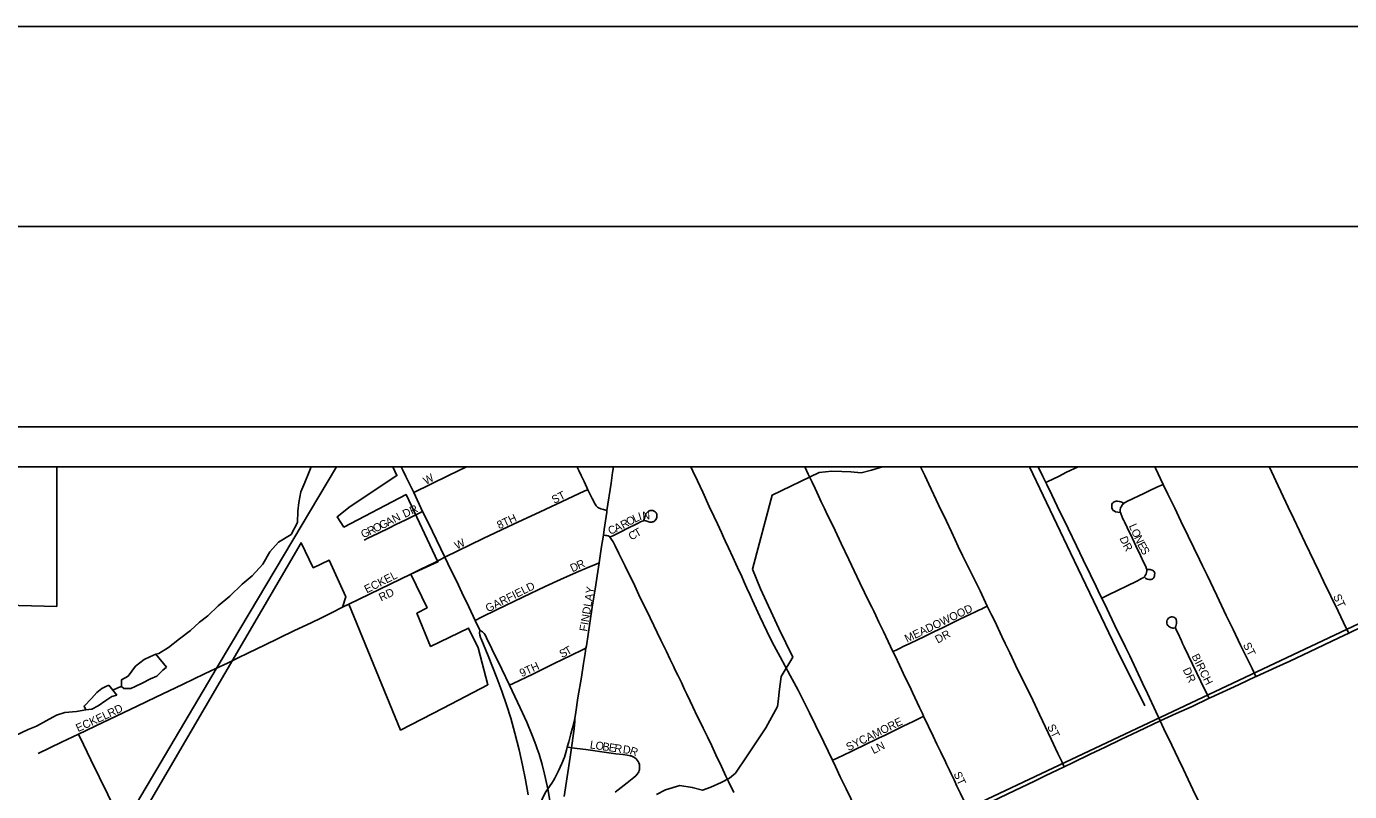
# Model space of a CAD drawing. Extents: x -5.6 to 34, y 0 to 22.
# Drawn here: x 3.152 to 6.458, y 20.089 to 22 of the extents above; entities that cross this region are included whole.
import ezdxf

# ---------------------------------------------------------------- set-up
doc = ezdxf.new("R2010")
doc.units = 0
for name, color, linetype in [('GM_X_City_Street', 7, 'Continuous'), ('GM_X_City_Street_Text', 7, 'Continuous'), ('GM_X_Corporation', 7, 'Continuous'), ('GM_X_Minor_Lake', 7, 'Continuous'), ('GM_X_Minor_River', 7, 'Continuous'), ('GM_X_Rail_Line', 7, 'Continuous'), ('GM_X_Section', 7, 'Continuous'), ('GM_X_State_Route', 7, 'Continuous'), ('GM_X_Township', 7, 'Continuous'), ('GM_X_Township_Road', 7, 'Continuous'), ('GM_X_Township_Subdivision', 7, 'Continuous'), ('GM_X_Township_Subdivision_Text', 7, 'Continuous'), ('SH_Border', 7, 'Continuous'), ('SH_Cut_Line', 7, 'Continuous'), ('SH_Data', 7, 'Continuous')]:
    doc.layers.add(name, color=color, linetype=linetype)

msp = doc.modelspace()

# ---------------------------------------------------------------- linework, layer by layer
at = {"layer": 'GM_X_City_Street'}
for points in [[(4.1194, 20.8356), (4.2063, 20.8782), (4.2512, 20.9)], [(4.5545, 20.8429), (4.5518, 20.8487), (4.5452, 20.8629), (4.5378, 20.8783), (4.5317, 20.8911), (4.5278, 20.8991), (4.5274, 20.9)], [(4.6024, 20.7906), (4.6129, 20.8588), (4.6166, 20.886), (4.6188, 20.9)], [(5.1659, 20.1669), (5.1441, 20.2122), (5.1236, 20.255), (5.1089, 20.2857), (5.0887, 20.3252), (5.0799, 20.3422), (5.0607, 20.379), (5.0351, 20.4251), (5.0153, 20.4621), (5.0021, 20.4891), (4.9845, 20.526), (4.9702, 20.557), (4.9658, 20.5664), (4.9599, 20.5793), (4.952, 20.5972), (4.9455, 20.6121), (4.9391, 20.6259), (4.9284, 20.6485), (4.9242, 20.6579), (4.9167, 20.6746), (4.9064, 20.6975), (4.8982, 20.7148), (4.8938, 20.7239), (4.8885, 20.7355), (4.8784, 20.7572), (4.8693, 20.7764), (4.8581, 20.8008), (4.8417, 20.8365), (4.8285, 20.865), (4.8168, 20.8893), (4.8118, 20.9)], [(5.3166, 20.4385), (5.2933, 20.4885), (5.2821, 20.5119), (5.2742, 20.5289), (5.2692, 20.5397), (5.2645, 20.5494), (5.2587, 20.5605), (5.2463, 20.5863), (5.2346, 20.6098), (5.2205, 20.6402), (5.2073, 20.6684), (5.188, 20.7085), (5.1726, 20.7406), (5.16, 20.7666), (5.1538, 20.7795), (5.1459, 20.7957), (5.1374, 20.8129), (5.131, 20.8276), (5.1227, 20.8455), (5.1151, 20.8613), (5.1052, 20.8815), (5.0966, 20.9)], [(5.553, 20.552), (5.535, 20.5898), (5.5237, 20.6135), (5.511, 20.6388), (5.4996, 20.6619), (5.4914, 20.6783), (5.4805, 20.701), (5.4723, 20.7178), (5.4637, 20.7377), (5.4508, 20.7638), (5.431, 20.8054), (5.4066, 20.8564), (5.3965, 20.8781), (5.386, 20.9)], [(5.6989, 20.8611), (5.7043, 20.8637), (5.7306, 20.8761), (5.7512, 20.8863), (5.7799, 20.9)], [(5.9923, 20.8561), (5.973, 20.8965), (5.9713, 20.9)], [(6.4565, 20.4841), (6.4502, 20.4971), (6.4295, 20.5397), (6.4113, 20.5772), (6.3931, 20.6147), (6.3806, 20.6406), (6.3697, 20.6631), (6.3473, 20.7097), (6.3187, 20.7701), (6.3047, 20.7996), (6.2739, 20.8646), (6.258, 20.8994), (6.2578, 20.9)], [(4.1976, 20.674), (4.2932, 20.7208), (4.3687, 20.7564), (4.4358, 20.7877), (4.5026, 20.8188), (4.5474, 20.8396), (4.5545, 20.8429)], [(4.6024, 20.7906), (4.5938, 20.7931), (4.5868, 20.7951), (4.5815, 20.7972), (4.5786, 20.7992), (4.5753, 20.8027), (4.5728, 20.8067), (4.5655, 20.8207), (4.5614, 20.8289), (4.5596, 20.8323), (4.5562, 20.8393), (4.5545, 20.8429)], [(5.894, 20.8086), (5.8959, 20.8099), (5.9038, 20.8144), (5.9155, 20.8198), (5.9332, 20.8282), (5.9429, 20.8327), (5.9578, 20.8398), (5.9771, 20.8489), (5.9923, 20.8561)], [(6.2245, 20.3762), (6.2148, 20.3959), (6.1859, 20.4547), (6.1676, 20.4932), (6.1504, 20.5287), (6.1263, 20.5789), (6.1022, 20.6292), (6.0905, 20.6527), (6.0831, 20.6682), (6.0547, 20.7271), (6.0367, 20.7645), (6.0213, 20.7964), (6.0041, 20.8314), (5.9923, 20.8561)], [(5.8855, 20.7861), (5.8789, 20.7867), (5.8737, 20.7879), (5.8699, 20.7897), (5.8676, 20.7912), (5.8657, 20.7936), (5.8645, 20.7975), (5.864, 20.8011), (5.8641, 20.8039), (5.8646, 20.8067), (5.8659, 20.8092), (5.8672, 20.8106), (5.8697, 20.8125), (5.8726, 20.8137), (5.8752, 20.814), (5.878, 20.8141), (5.8829, 20.8134), (5.8867, 20.8124), (5.8905, 20.8108), (5.894, 20.8086)], [(5.8855, 20.7861), (5.8852, 20.7893), (5.8852, 20.7911), (5.8854, 20.7929), (5.8863, 20.7973), (5.8881, 20.801), (5.8902, 20.8048), (5.894, 20.8086)], [(4.5934, 20.7292), (4.5956, 20.7437), (4.6018, 20.7866), (4.6024, 20.7906)], [(4.6099, 20.724), (4.6205, 20.7294), (4.6334, 20.736), (4.6578, 20.7482), (4.6721, 20.7554), (4.68, 20.7596), (4.686, 20.7627), (4.6902, 20.7643), (4.6937, 20.7654), (4.6966, 20.7656), (4.6995, 20.7653), (4.7048, 20.7635), (4.7095, 20.762), (4.7111, 20.7618), (4.7129, 20.7617), (4.7147, 20.7619), (4.7163, 20.7623), (4.7178, 20.7628), (4.7195, 20.7636), (4.721, 20.7645), (4.7224, 20.7656), (4.7237, 20.7669), (4.7247, 20.7682), (4.7256, 20.7696), (4.7264, 20.7713), (4.727, 20.7731), (4.7272, 20.7746), (4.7274, 20.7764), (4.7274, 20.7781), (4.7271, 20.7799), (4.7267, 20.7815), (4.7261, 20.7831), (4.7253, 20.7847), (4.7244, 20.7861), (4.7232, 20.7874), (4.7205, 20.7893), (4.7191, 20.7899), (4.7172, 20.7905), (4.7137, 20.7911), (4.7103, 20.7908), (4.7087, 20.7904), (4.7071, 20.7897), (4.7055, 20.7887), (4.7043, 20.7878), (4.7018, 20.7852), (4.6999, 20.7827), (4.6987, 20.7803), (4.6981, 20.7787), (4.6975, 20.7772), (4.6948, 20.7663)], [(5.9513, 20.6438), (5.951, 20.6454), (5.9489, 20.651), (5.9437, 20.6619), (5.9356, 20.6788), (5.924, 20.703), (5.9155, 20.721), (5.9025, 20.7482), (5.8955, 20.7627), (5.8941, 20.7656), (5.8921, 20.7698), (5.8864, 20.7831), (5.8855, 20.7861)], [(4.583, 20.6603), (4.5891, 20.7009), (4.5934, 20.7292)], [(4.6099, 20.724), (4.6093, 20.7247), (4.6074, 20.7264), (4.6051, 20.7277), (4.6022, 20.7283), (4.5985, 20.7287), (4.5934, 20.7292)], [(4.9193, 20.0864), (4.9062, 20.1142), (4.8997, 20.1274), (4.8886, 20.1512), (4.8749, 20.1806), (4.8645, 20.2028), (4.8536, 20.2251), (4.8428, 20.247), (4.837, 20.2593), (4.8282, 20.2774), (4.8173, 20.3), (4.81, 20.3146), (4.8018, 20.3319), (4.7965, 20.3436), (4.7883, 20.3609), (4.7793, 20.3798), (4.7724, 20.3939), (4.7685, 20.4022), (4.7607, 20.4188), (4.7512, 20.4389), (4.7374, 20.467), (4.7105, 20.5225), (4.6824, 20.5804), (4.6684, 20.61), (4.6578, 20.6312), (4.6478, 20.6517), (4.6322, 20.6837), (4.623, 20.7022), (4.6176, 20.7122), (4.6152, 20.7162), (4.6123, 20.7209), (4.6099, 20.724)], [(4.1119, 20.6319), (4.1355, 20.6433), (4.1719, 20.661), (4.1976, 20.674)], [(4.273, 20.516), (4.289, 20.524), (4.3261, 20.5426), (4.3919, 20.5743), (4.4478, 20.6007), (4.4861, 20.6183), (4.5252, 20.636), (4.5532, 20.648), (4.5751, 20.6571), (4.583, 20.6603)], [(4.55, 20.4468), (4.5509, 20.4531), (4.5552, 20.4809), (4.5656, 20.5496), (4.5731, 20.594), (4.5796, 20.6382), (4.583, 20.6603)], [(5.9451, 20.6251), (5.9467, 20.6269), (5.9479, 20.6286), (5.949, 20.6307), (5.95, 20.6328), (5.9509, 20.6356), (5.9515, 20.6398), (5.9515, 20.6426), (5.9513, 20.6438)], [(5.9451, 20.6251), (5.9494, 20.6209), (5.951, 20.6199), (5.953, 20.619), (5.9568, 20.6182), (5.9598, 20.6182), (5.9625, 20.6187), (5.9647, 20.6195), (5.9662, 20.6203), (5.9664, 20.6204), (5.9682, 20.6222), (5.9693, 20.6236), (5.9706, 20.6268), (5.9712, 20.6302), (5.9713, 20.6339), (5.9708, 20.6362), (5.9697, 20.6383), (5.9682, 20.64), (5.9667, 20.6411), (5.965, 20.6421), (5.9629, 20.643), (5.9597, 20.6436), (5.9551, 20.6437), (5.9513, 20.6438)], [(3.9572, 20.5568), (4.0086, 20.5819), (4.0863, 20.619), (4.1119, 20.6319)], [(5.839, 20.5716), (5.8527, 20.5783), (5.8819, 20.5926), (5.8995, 20.601), (5.9283, 20.6155), (5.9342, 20.6183), (5.9387, 20.6208), (5.9422, 20.6228), (5.9451, 20.6251)], [(3.6544, 20.4098), (3.679, 20.4217), (3.7069, 20.4354), (3.7462, 20.4547), (3.8196, 20.49), (3.8648, 20.5113), (3.887, 20.5219), (3.9138, 20.535), (3.9415, 20.549)], [(5.3166, 20.4385), (5.3248, 20.4423), (5.3336, 20.4464), (5.3427, 20.4509), (5.3592, 20.4589), (5.396, 20.476), (5.4195, 20.4874), (5.443, 20.499), (5.4842, 20.519), (5.5113, 20.532), (5.522, 20.537), (5.5338, 20.5424), (5.5385, 20.5446), (5.543, 20.5469), (5.553, 20.552)], [(5.7452, 20.1506), (5.7398, 20.1623), (5.7296, 20.1841), (5.7127, 20.22), (5.6838, 20.281), (5.6619, 20.3275), (5.6393, 20.3724), (5.6237, 20.4044), (5.609, 20.4351), (5.5979, 20.4589), (5.5894, 20.4765), (5.5715, 20.5144), (5.5634, 20.5303), (5.553, 20.552)], [(6.1071, 20.3217), (6.0979, 20.3409), (6.0452, 20.45), (6.0412, 20.4589), (6.0387, 20.4649), (6.0289, 20.4855), (6.0245, 20.4944), (6.0239, 20.4963), (6.0234, 20.4992), (6.0235, 20.5006), (6.0238, 20.502), (6.0247, 20.505), (6.0258, 20.5085), (6.0262, 20.511), (6.0262, 20.5144), (6.0254, 20.5187), (6.0238, 20.5212), (6.0215, 20.523), (6.0189, 20.5245), (6.0159, 20.525), (6.0137, 20.525), (6.011, 20.5246), (6.0084, 20.5236), (6.0061, 20.5219), (6.0042, 20.5198), (6.0028, 20.5174), (6.002, 20.5147), (6.0021, 20.509), (6.0028, 20.5064), (6.0042, 20.5039), (6.0061, 20.5018), (6.0084, 20.5001), (6.0112, 20.4987), (6.014, 20.4978), (6.0168, 20.4973), (6.019, 20.4972), (6.0226, 20.4974)], [(6.2245, 20.3762), (6.2247, 20.3763), (6.2755, 20.3995), (6.3087, 20.4147), (6.3582, 20.4374), (6.4318, 20.4724), (6.4565, 20.4841)], [(6.4565, 20.4841), (6.4603, 20.4858), (6.4871, 20.4992)], [(4.3589, 20.3542), (4.3677, 20.3585), (4.4168, 20.3824), (4.4707, 20.4085), (4.512, 20.4284), (4.543, 20.4434), (4.55, 20.4468)], [(4.5218, 20.2715), (4.5242, 20.287), (4.5299, 20.3233), (4.5386, 20.3744), (4.5441, 20.4084), (4.548, 20.4339), (4.55, 20.4468)], [(5.3938, 20.2769), (5.3907, 20.2836), (5.3833, 20.2989), (5.3663, 20.3358), (5.359, 20.3511), (5.3481, 20.3736), (5.3335, 20.4041), (5.3223, 20.4275), (5.3166, 20.4385)], [(3.2812, 20.2325), (3.3422, 20.2613), (3.4284, 20.3019), (3.475, 20.3242), (3.5416, 20.3562), (3.5964, 20.383), (3.6247, 20.3962), (3.6544, 20.4098)], [(6.1071, 20.3217), (6.1114, 20.3238), (6.1806, 20.3557), (6.2245, 20.3762)], [(5.9848, 20.2651), (6.0253, 20.2835), (6.0652, 20.3016), (6.1071, 20.3217)], [(4.5033, 20.1995), (4.5072, 20.2127), (4.5124, 20.2331), (4.516, 20.2477), (4.5218, 20.2715)], [(4.5139, 20.1982), (4.5188, 20.2342), (4.5202, 20.2453), (4.5213, 20.2557), (4.5217, 20.2633), (4.5218, 20.2715)], [(5.1659, 20.1669), (5.1779, 20.1725), (5.2131, 20.1892), (5.2549, 20.2094), (5.2691, 20.2163), (5.2828, 20.2227), (5.2959, 20.2289), (5.3214, 20.2413), (5.3428, 20.2517), (5.3676, 20.2637), (5.3873, 20.2736), (5.3938, 20.2769)], [(5.5095, 20.0372), (5.5046, 20.0469), (5.4971, 20.0616), (5.486, 20.0842), (5.4772, 20.1026), (5.4698, 20.1182), (5.4634, 20.1313), (5.4585, 20.1426), (5.4546, 20.1507), (5.4514, 20.1574), (5.4467, 20.1668), (5.4405, 20.1797), (5.4368, 20.1873), (5.427, 20.2075), (5.4179, 20.2268), (5.3946, 20.2753), (5.3938, 20.2769)], [(5.8869, 20.2187), (5.9291, 20.2387), (5.9848, 20.2651)], [(3.2812, 20.2325), (3.2388, 20.212), (3.1809, 20.184)], [(3.4074, 19.9733), (3.3902, 20.0079), (3.3759, 20.0378), (3.3552, 20.0811), (3.3122, 20.168), (3.2939, 20.2059), (3.2812, 20.2325)], [(5.8103, 20.1819), (5.8473, 20.1998), (5.8869, 20.2187)], [(4.4544, 20.0959), (4.4645, 20.1101), (4.4686, 20.1164), (4.4719, 20.1219), (4.4813, 20.1402), (4.4897, 20.1588), (4.4959, 20.175), (4.5012, 20.192), (4.5033, 20.1995)], [(4.4957, 20.0768), (4.5106, 20.1745), (4.5139, 20.1982)], [(4.5139, 20.1982), (4.5092, 20.1988), (4.5033, 20.1995)], [(4.623, 20.087), (4.6533, 20.1103), (4.6696, 20.1236), (4.6745, 20.1281), (4.6781, 20.1323), (4.6803, 20.1358), (4.6818, 20.1382), (4.6828, 20.1411), (4.6834, 20.1437), (4.6838, 20.1466), (4.6839, 20.1514), (4.6838, 20.1541), (4.6834, 20.1567), (4.6822, 20.1603), (4.6804, 20.1637), (4.6782, 20.1669), (4.6753, 20.1703), (4.6718, 20.1731), (4.6694, 20.1747), (4.6663, 20.1762), (4.6627, 20.1776), (4.66, 20.1782), (4.6531, 20.1794), (4.6418, 20.181), (4.6249, 20.1833), (4.6067, 20.1859), (4.5496, 20.1935), (4.5139, 20.1982)], [(5.7452, 20.1506), (5.7657, 20.1604), (5.8103, 20.1819)], [(5.2807, 19.9276), (5.2755, 19.9386), (5.2656, 19.9593), (5.2256, 20.042), (5.2118, 20.071), (5.2001, 20.0953), (5.1855, 20.1258), (5.1734, 20.1513), (5.1659, 20.1669)], [(5.6976, 20.1278), (5.7452, 20.1506)], [(5.5095, 20.0372), (5.5196, 20.042), (5.6047, 20.0832), (5.671, 20.1151), (5.6976, 20.1278)], [(4.4187, 19.9793), (4.4216, 19.9958), (4.4283, 20.0312), (4.4317, 20.045), (4.4361, 20.0589), (4.4405, 20.0696), (4.4447, 20.0787), (4.4499, 20.0884), (4.4544, 20.0959)]]:
    msp.add_lwpolyline(points, dxfattribs=at)
at = {"layer": 'GM_X_Corporation'}
for points in [[(2.8151, 20.562), (3.2274, 20.5511), (3.2277, 20.9), (2.1, 20.9)], [(8.2067, 20.9), (4.0671, 20.9), (4.0774, 20.8782), (3.9603, 20.8011), (3.9283, 20.7752), (3.945, 20.7493), (4.1004, 20.8306), (4.1798, 20.6626), (4.1119, 20.6319), (4.1528, 20.5478), (4.1273, 20.534), (4.1616, 20.4512), (4.2565, 20.497), (4.2803, 20.4477), (4.3047, 20.3554), (4.1931, 20.2971), (4.0865, 20.2422), (3.9572, 20.5568), (3.9415, 20.549), (3.9497, 20.5751), (3.9081, 20.6665), (3.8684, 20.6477), (3.8378, 20.7105), (3.4074, 19.9733)]]:
    msp.add_lwpolyline(points, dxfattribs=at)
at = {"layer": 'GM_X_Minor_Lake'}
for p, q in [((3.5016, 20.3991), (3.4752, 20.4318)), ((3.3778, 20.3299), (3.3576, 20.3544))]:
    msp.add_line(p, q, dxfattribs=at)
for points in [[(3.4752, 20.4318), (3.4599, 20.4257), (3.4454, 20.4189), (3.4242, 20.4017), (3.4061, 20.3773), (3.3891, 20.3681), (3.3887, 20.3513), (3.3949, 20.3463), (3.4125, 20.3459), (3.423, 20.3512), (3.4408, 20.3596), (3.4618, 20.3703), (3.4771, 20.3772), (3.4926, 20.392), (3.5016, 20.3991)], [(3.3576, 20.3544), (3.3503, 20.3514), (3.3398, 20.346), (3.3276, 20.3359), (3.3137, 20.321), (3.2956, 20.3022), (3.3002, 20.2933), (3.3146, 20.2945), (3.3308, 20.3029), (3.3503, 20.3161), (3.3649, 20.3262), (3.3778, 20.3299)]]:
    msp.add_lwpolyline(points, dxfattribs=at)
at = {"layer": 'GM_X_Minor_River'}
for points in [[(3.8635, 20.9), (3.8581, 20.8878), (3.8472, 20.8607), (3.8372, 20.8376), (3.8319, 20.8105), (3.8299, 20.7889), (3.8286, 20.7608), (3.8129, 20.7306), (3.7814, 20.712), (3.7602, 20.6875), (3.7421, 20.6566), (3.716, 20.6274), (3.6908, 20.607), (3.6599, 20.5771), (3.6308, 20.5528), (3.6047, 20.5276), (3.5837, 20.512), (3.5618, 20.4915), (3.5342, 20.4704), (3.5067, 20.4484), (3.4825, 20.4336)], [(5.2909, 20.9), (5.2638, 20.8913), (5.2374, 20.8853), (5.2119, 20.8874), (5.1896, 20.8886), (5.1648, 20.8891), (5.1328, 20.8857)], [(5.6582, 20.9), (5.7611, 20.685), (5.8761, 20.4454), (5.9468, 20.3027)], [(5.1328, 20.8857), (5.0152, 20.8293), (4.9663, 20.6442), (4.9861, 20.5949), (5.0322, 20.4962), (5.0667, 20.4242), (5.0379, 20.3758), (5.0324, 20.3382), (5.0313, 20.3206), (5.0285, 20.3014), (4.9996, 20.2482), (4.9528, 20.1777), (4.9239, 20.1351)], [(3.4825, 20.4336), (3.4752, 20.4318)], [(3.3887, 20.3513), (3.3815, 20.3486), (3.3678, 20.342)], [(3.2762, 20.2891), (3.2474, 20.2865), (3.2265, 20.2796), (3.2007, 20.2657), (3.1765, 20.2525), (3.1556, 20.2441), (3.1226, 20.2278)], [(3.2762, 20.2891), (3.3002, 20.2933)], [(4.9239, 20.1351), (4.9086, 20.1224), (4.8877, 20.1115), (4.8619, 20.1), (4.841, 20.0924), (4.8156, 20.0993), (4.7846, 20.1038), (4.7484, 20.0933), (4.7259, 20.0817)]]:
    msp.add_lwpolyline(points, dxfattribs=at)
at = {"layer": 'GM_X_Rail_Line'}
msp.add_line((3.664, 20.4592), (3.9268, 20.9), dxfattribs=at)
for points in [[(3.6284, 20.3994), (3.664, 20.4592)], [(2.1, 17.8198), (3.0599, 19.4414), (3.6284, 20.3994)]]:
    msp.add_lwpolyline(points, dxfattribs=at)
at = {"layer": 'GM_X_Section'}
msp.add_lwpolyline([(7.5006, 20.9), (7.2498, 20.9), (7.2609, 20.8761), (5.343, 19.9706), (5.3166, 18.9352), (7.4578, 18.9294)], close=True, dxfattribs=at)
at = {"layer": 'GM_X_State_Route'}
for points in [[(4.1976, 20.674), (4.166, 20.7383), (4.1535, 20.7639), (4.1415, 20.7884), (4.1194, 20.8356), (4.0995, 20.8762), (4.0921, 20.8918), (4.0881, 20.9)], [(5.9848, 20.2651), (5.9741, 20.2891), (5.9533, 20.334), (5.9411, 20.3598), (5.9091, 20.4274), (5.8981, 20.4497), (5.8711, 20.5051), (5.8524, 20.5442), (5.839, 20.5716), (5.8351, 20.5796), (5.8249, 20.6009), (5.8108, 20.6305), (5.7928, 20.6677), (5.776, 20.7026), (5.7548, 20.7461), (5.7278, 20.8015), (5.7141, 20.8298), (5.7015, 20.8558), (5.6989, 20.8611), (5.6919, 20.8759), (5.6803, 20.9)], [(4.2843, 20.4923), (4.273, 20.516), (4.2569, 20.55), (4.2399, 20.586), (4.2268, 20.6131), (4.2125, 20.6425), (4.1976, 20.674)], [(4.4056, 20.0807), (4.3991, 20.1183), (4.3917, 20.1544), (4.3829, 20.1929), (4.3721, 20.2349), (4.3618, 20.2717), (4.3513, 20.3056), (4.3398, 20.3392), (4.3273, 20.3725), (4.3058, 20.4276), (4.288, 20.47), (4.2864, 20.4736), (4.2849, 20.4792), (4.284, 20.4849), (4.2843, 20.4923)], [(4.4282, 20.1958), (4.425, 20.2054), (4.4166, 20.2274), (4.4019, 20.2625), (4.3856, 20.2983), (4.3589, 20.3542), (4.3398, 20.3943), (4.315, 20.4451), (4.3012, 20.4728), (4.2977, 20.48), (4.2953, 20.4837), (4.2932, 20.4858), (4.2914, 20.4875), (4.2893, 20.489), (4.2843, 20.4923)], [(6.2598, 19.7018), (6.2585, 19.7045), (6.2346, 19.7539), (6.2004, 19.8223), (6.1853, 19.8534), (6.1683, 19.8884), (6.1626, 19.9001), (6.1376, 19.9509), (6.1205, 19.9849), (6.1186, 19.9886), (6.0996, 20.0257), (6.0669, 20.0942), (6.0432, 20.1438), (6.0306, 20.1698), (6.0139, 20.2049), (5.9946, 20.2455), (5.9848, 20.2651)], [(4.4698, 19.9432), (4.4699, 19.9524), (4.469, 19.971), (4.4675, 19.9954), (4.4655, 20.0203), (4.4623, 20.0489), (4.4582, 20.0761), (4.4544, 20.0959), (4.453, 20.1032), (4.4466, 20.1326), (4.4403, 20.1567), (4.4328, 20.1818), (4.4282, 20.1958)]]:
    msp.add_lwpolyline(points, dxfattribs=at)
at = {"layer": 'GM_X_Township'}
msp.add_lwpolyline([(3.0636, 14.1), (8.9, 14.1), (8.9, 20.9), (2.1, 20.9), (2.1, 16.9108), (2.7242, 16.8707), (3.1388, 16.8616), (3.0745, 14.7121)], close=True, dxfattribs=at)
at = {"layer": 'GM_X_Township_Road'}
msp.add_lwpolyline([(3.9415, 20.549), (3.9482, 20.5523), (3.9572, 20.5568)], dxfattribs=at)
at = {"layer": 'GM_X_Township_Subdivision'}
for points in [[(4.059, 20.7477), (4.0747, 20.7559), (4.0994, 20.7678), (4.1415, 20.7884)], [(3.9957, 20.7169), (4.0051, 20.7215), (4.0169, 20.7272), (4.0298, 20.7335), (4.059, 20.7477)]]:
    msp.add_lwpolyline(points, dxfattribs=at)
at = {"layer": 'SH_Border'}
msp.add_lwpolyline([(1.5, 21.5), (33.5, 21.5), (33.5, 0.5), (1.5, 0.5)], close=True, dxfattribs=at)
at = {"layer": 'SH_Cut_Line'}
msp.add_lwpolyline([(0, 0), (34, 0), (34, 22), (0, 22)], close=True, dxfattribs=at)
at = {"layer": 'SH_Data'}
for p, q in [((2, 21), (9, 21)), ((2.1, 20.9), (8.9, 20.9))]:
    msp.add_line(p, q, dxfattribs=at)

# ---------------------------------------------------------------- texts
at = {"layer": 'GM_X_City_Street_Text'}
for s, rotation, p in [('W', 28.6091, (4.1499, 20.8546)), ('ST', 26.565, (4.4703, 20.8072)), ('8TH', 25.115, (4.3331, 20.7439)), ('R', 28.4507, (4.6428, 20.7444)), ('O', 28.2756, (4.6568, 20.7519)), ('L', 24.8419, (4.672, 20.7601)), ('I', 17.2602, (4.6841, 20.7658)), ('N', 2.4051, (4.6912, 20.7681)), ('C', 21.2467, (4.6097, 20.7299)), ('A', 25.432, (4.6259, 20.7363)), ('C', 29.7268, (4.6632, 20.7156)), ('T', 29.1077, (4.6769, 20.7234)), ('L', 294.0346, (5.9063, 20.7526)), ('O', 294.0224, (5.912, 20.7397)), ('W', 26.5505, (4.2274, 20.6928)), ('D', 292.3492, (5.8831, 20.7218)), ('R', 299.4549, (5.8909, 20.7031)), ('N', 294.5811, (5.9193, 20.7234)), ('E', 298.3171, (5.9272, 20.7061)), ('R', 23.3708, (4.5318, 20.6437)), ('S', 299.6555, (5.9342, 20.6933)), ('ECKEL', 26.5607, (4.0021, 20.5837)), ('D', 24.5905, (4.5159, 20.6364)), ('GARFIELD', 26.5636, (4.3049, 20.5362)), ('FINDLAY', 80.5359, (4.5528, 20.4876)), ('RD', 25.2123, (4.0378, 20.5635)), ('ST', 295.0177, (6.4167, 20.5766)), ('MEADOWOOD', 25.4865, (5.3522, 20.4605)), ('DR', 27.8805, (5.429, 20.4582)), ('S', 26.9072, (4.4897, 20.4218)), ('T', 29.0898, (4.503, 20.4285)), ('ST', 296.5651, (6.1914, 20.4553)), ('9TH', 24.6351, (4.3894, 20.3743)), ('BIRCH', 296.5651, (6.0629, 20.4271)), ('DR', 295.2018, (6.0409, 20.3932)), ('RD', 25.1968, (3.3598, 20.2739)), ('ECKEL', 24.8647, (3.2806, 20.237)), ('SYCAMORE', 26.2396, (5.2061, 20.1895)), ('ST', 296.5651, (5.7021, 20.2511)), ('L', 351.6111, (4.5588, 20.1968)), ('O', 351.5979, (4.5727, 20.1948)), ('B', 351.5917, (4.5901, 20.1922)), ('E', 351.6056, (4.6058, 20.1899)), ('R', 351.6265, (4.6197, 20.1878)), ('LN', 26.5699, (5.2687, 20.1819)), ('D', 353.2998, (4.6413, 20.1847)), ('R', 339.7907, (4.6576, 20.1829)), ('ST', 295.0177, (5.468, 20.1331))]:
    msp.add_text(s, height=0.02, rotation=rotation, dxfattribs=at).set_placement(p)
at = {"layer": 'GM_X_Township_Subdivision_Text'}
for s, rotation, p in [('DR', 25.2017, (4.0973, 20.772)), ('G', 26.0666, (4.0392, 20.7434)), ('A', 26.3837, (4.0551, 20.7512)), ('N', 28.4352, (4.0716, 20.7594)), ('G', 26.0666, (3.9934, 20.721)), ('R', 26.0719, (4.0092, 20.7287)), ('O', 26.0664, (4.0234, 20.7357))]:
    msp.add_text(s, height=0.02, rotation=rotation, dxfattribs=at).set_placement(p)

doc.saveas('drawing.dxf')
